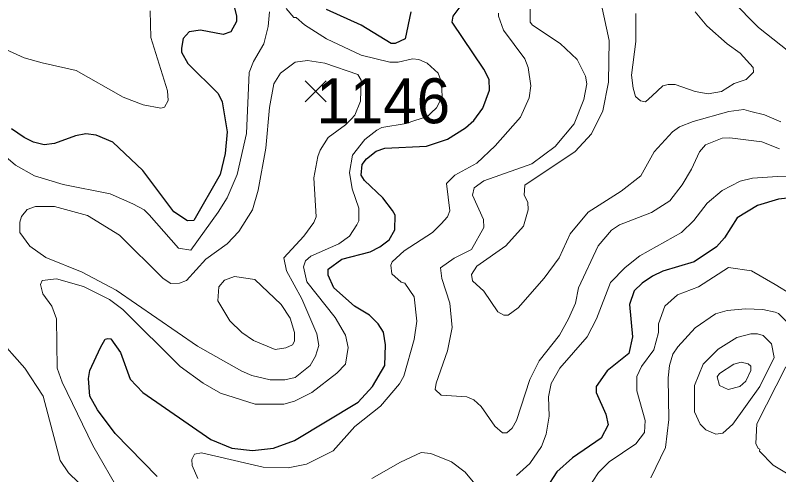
# Model space of a CAD drawing. Extents: x 423 to 448.8, y 7456.3 to 7484.
# Drawn here: x 423.744 to 425.103, y 7470.707 to 7471.525 of the extents above; entities that cross this region are included whole.
import ezdxf
from ezdxf.enums import TextEntityAlignment as Align

# ---------------------------------------------------------------- set-up
doc = ezdxf.new("R2010")
doc.units = 0
doc.header["$LTSCALE"] = 0.032
for name, color, linetype, lineweight in [('1', 7, 'Continuous', 25), ('2', 7, 'Continuous', 13), ('21', 7, 'Continuous', 25)]:
    doc.layers.add(name, color=color, linetype=linetype, lineweight=lineweight)
doc.layers.add('61', color=7, linetype='Continuous')

msp = doc.modelspace()

# ---------------------------------------------------------------- linework, layer by layer
at = {"layer": '1'}
for points in [[(424.1238, 7471.5788), (424.1378, 7471.5231), (424.1378, 7471.5138), (424.1277, 7471.4952), (424.1138, 7471.4906), (424.0736, 7471.4984), (424.0535, 7471.4953), (424.0426, 7471.4836), (424.0395, 7471.4659), (424.0395, 7471.4589), (424.0512, 7471.4388), (424.1053, 7471.3854), (424.1122, 7471.3707), (424.1208, 7471.3174), (424.1177, 7471.2787), (424.1084, 7471.2416), (424.062, 7471.1596), (424.0504, 7471.1588), (424.0264, 7471.175), (423.9707, 7471.2485), (423.9174, 7471.2988), (423.888, 7471.3112), (423.8694, 7471.3135), (423.8509, 7471.3104), (423.8137, 7471.2965), (423.7952, 7471.2941), (423.7766, 7471.2988), (423.7595, 7471.3073), (423.7371, 7471.3228)], [(423.9962, 7470.704), (423.922, 7470.7806), (423.8903, 7470.8224), (423.8764, 7470.8471), (423.874, 7470.8781), (423.8764, 7470.8927), (423.8957, 7470.9337), (423.9037, 7470.9485), (423.9084, 7470.9493), (423.9089, 7470.9493), (423.9143, 7470.9492), (423.9313, 7470.9245), (423.9483, 7470.8773), (423.9707, 7470.8533), (424.0922, 7470.7698), (424.1293, 7470.7543), (424.1664, 7470.7504), (424.2036, 7470.7543), (424.2407, 7470.7682), (424.3544, 7470.8363), (424.3799, 7470.8641), (424.4015, 7470.9013), (424.4031, 7470.9384), (424.3992, 7470.9608), (424.3899, 7470.9755), (424.3745, 7470.991), (424.3474, 7471.0072), (424.3111, 7471.0397), (424.301, 7471.0621), (424.301, 7471.073), (424.325, 7471.0907), (424.3753, 7471.1039), (424.393, 7471.1124), (424.4092, 7471.1248), (424.4193, 7471.1426), (424.4201, 7471.1688), (424.4155, 7471.1774), (424.3984, 7471.1998), (424.3652, 7471.2307), (424.3598, 7471.24), (424.3613, 7471.2593), (424.369, 7471.2694), (424.3861, 7471.2826), (424.4016, 7471.288), (424.4758, 7471.2918), (424.5129, 7471.3042), (424.5454, 7471.3243), (424.5601, 7471.3375), (424.5763, 7471.3591), (424.588, 7471.3916), (424.5872, 7471.4102), (424.5779, 7471.4288), (424.5214, 7471.5123), (424.523, 7471.5231), (424.5516, 7471.5618)], [(424.448, 7471.5309), (424.4379, 7471.4829), (424.4201, 7471.4744), (424.4131, 7471.4744), (424.3598, 7471.5069), (424.2979, 7471.5347)], [(425.1394, 7471.2014), (425.1023, 7471.1975), (425.0652, 7471.1859), (425.0288, 7471.1642), (425.0064, 7471.1287), (424.9917, 7471.1124), (424.9523, 7471.0861), (424.8966, 7471.0691), (424.878, 7471.0606), (424.8594, 7471.0482), (424.8455, 7471.0343), (424.837, 7471.0103), (424.8424, 7470.9523), (424.8362, 7470.9229), (424.7976, 7470.8919), (424.7775, 7470.8641), (424.7775, 7470.8533), (424.7952, 7470.8146), (424.7991, 7470.7961), (424.7867, 7470.7721), (424.7357, 7470.7373), (424.7078, 7470.7125), (424.6893, 7470.6839)]]:
    msp.add_lwpolyline(points, dxfattribs=at)
at = {"layer": '2'}
for points in [[(424.7867, 7471.5455), (424.8007, 7471.4798), (424.7999, 7471.4056), (424.7898, 7471.3545), (424.7697, 7471.3135), (424.7403, 7471.2825), (424.6506, 7471.2222), (424.6498, 7471.2045), (424.656, 7471.1921), (424.6568, 7471.1782), (424.6483, 7471.1495), (424.6173, 7471.1147), (424.5655, 7471.0784), (424.5562, 7471.0637)], [(425.1317, 7471.4512), (425.0667, 7471.503), (425.0195, 7471.551)], [(423.9839, 7471.5324), (423.9854, 7471.4852), (424.0148, 7471.3901), (424.0163, 7471.3731), (424.0094, 7471.3614), (424.0032, 7471.3591), (423.9715, 7471.3653), (423.9359, 7471.3792), (423.8524, 7471.4264), (423.7921, 7471.4403), (423.7596, 7471.4488), (423.7271, 7471.4635), (423.6513, 7471.5138), (423.618, 7471.5293)], [(424.226, 7471.537), (424.2399, 7471.5208), (424.2438, 7471.5208), (424.2585, 7471.5077), (424.2979, 7471.4829), (424.3598, 7471.4535), (424.4108, 7471.4411), (424.4255, 7471.4411), (424.4511, 7471.4473), (424.4619, 7471.4458), (424.4773, 7471.4396), (424.4967, 7471.4218), (424.5027, 7471.4057), (424.5035, 7471.3794), (424.4936, 7471.3598), (424.4839, 7471.3512), (424.4783, 7471.3452), (424.474, 7471.3435), (424.455, 7471.3375), (424.4396, 7471.3322), (424.3961, 7471.3247), (424.3876, 7471.3205), (424.366, 7471.3034), (424.3443, 7471.2756), (424.3389, 7471.2447), (424.3435, 7471.216), (424.3551, 7471.1813), (424.3551, 7471.1588), (424.3521, 7471.1519), (424.3389, 7471.1317), (424.3195, 7471.1178), (424.2701, 7471.0961), (424.2607, 7471.0876), (424.2569, 7471.0768), (424.2631, 7471.0505), (424.3133, 7470.9871), (424.3319, 7470.9554), (424.3366, 7470.9337), (424.3319, 7470.9036), (424.3165, 7470.8881), (424.2716, 7470.8533), (424.2407, 7470.8378), (424.2221, 7470.8324), (424.1711, 7470.8324), (424.1092, 7470.8525), (424.0783, 7470.8703), (424.0372, 7470.8997), (423.9351, 7471.001), (423.9119, 7471.0188), (423.8655, 7471.042), (423.8176, 7471.0559), (423.7921, 7471.0529), (423.789, 7471.0459), (423.7928, 7471.0289)], [(424.6606, 7471.5355), (424.6606, 7471.5123), (424.6645, 7471.5069), (424.714, 7471.4744), (424.7442, 7471.4458), (424.7589, 7471.4164), (424.7612, 7471.4025), (424.7558, 7471.3746), (424.7387, 7471.3313), (424.7048, 7471.291), (424.663, 7471.2601)], [(423.7054, 7471.2911), (423.7441, 7471.2578), (423.7782, 7471.2392), (423.8292, 7471.2238), (423.9127, 7471.2067), (423.953, 7471.189), (423.9731, 7471.1782), (423.9823, 7471.1696), (424.0342, 7471.1101), (424.0566, 7471.107), (424.1053, 7471.1743), (424.1208, 7471.1998), (424.1386, 7471.2416), (424.1556, 7471.3143), (424.1602, 7471.4226), (424.168, 7471.4427), (424.1865, 7471.4736), (424.1943, 7471.5046), (424.1966, 7471.5308)], [(424.6127, 7471.4983), (424.6042, 7471.5231), (424.6042, 7471.5285)], [(424.9538, 7471.5309), (424.9747, 7471.5061), (425.011, 7471.4736), (425.0342, 7471.4573), (425.0574, 7471.4318), (425.0578, 7471.4237), (425.045, 7471.4102), (425.0234, 7471.4032), (425.001, 7471.3893), (424.977, 7471.3847), (424.9538, 7471.3893), (424.9182, 7471.4017), (424.9059, 7471.4017), (424.8965, 7471.3993), (424.8772, 7471.3816), (424.8656, 7471.3707), (424.8564, 7471.3723), (424.8478, 7471.38), (424.8439, 7471.3947), (424.8409, 7471.4179), (424.8486, 7471.4783), (424.8486, 7471.5278)], [(424.069, 7470.7001), (424.0589, 7470.7234), (424.0581, 7470.7342), (424.0627, 7470.7434), (424.0752, 7470.7458), (424.185, 7470.7203), (424.2299, 7470.7195), (424.2623, 7470.7257), (424.3095, 7470.7496), (424.3482, 7470.793), (424.3938, 7470.8293), (424.4279, 7470.8687), (424.4356, 7470.8827), (424.4541, 7470.9477), (424.4588, 7470.9802), (424.4541, 7471.0235), (424.4371, 7471.0482), (424.4309, 7471.0498), (424.4139, 7471.0644), (424.4124, 7471.0799), (424.4147, 7471.0861), (424.4363, 7471.1055), (424.4866, 7471.1379), (424.5021, 7471.1534), (424.5129, 7471.1658), (424.5176, 7471.1766), (424.5114, 7471.2253), (424.5261, 7471.24), (424.5655, 7471.2617), (424.598, 7471.2926), (424.6429, 7471.3436), (424.6583, 7471.3777), (424.6614, 7471.3994), (424.6568, 7471.4319), (424.6506, 7471.4473), (424.6127, 7471.4983)], [(424.5562, 7471.0637), (424.5578, 7471.0521), (424.5779, 7471.0335), (424.6026, 7470.9971), (424.6135, 7470.9909), (424.6212, 7470.9909), (424.639, 7471.0041), (424.6854, 7471.0567), (424.7117, 7471.0931), (424.7318, 7471.1356), (424.7635, 7471.1743), (424.8223, 7471.2114), (424.8571, 7471.2392), (424.8811, 7471.2818), (424.9136, 7471.3173), (424.926, 7471.3259), (424.9507, 7471.3359), (425.0141, 7471.3537), (425.0404, 7471.3568), (425.0528, 7471.3537), (425.0776, 7471.3475), (425.1062, 7471.3351)], [(424.663, 7471.2601), (424.5779, 7471.23), (424.5609, 7471.2176), (424.5578, 7471.2045), (424.5771, 7471.1611), (424.5779, 7471.1472), (424.5562, 7471.1078), (424.5253, 7471.0923), (424.5006, 7471.0753), (424.5029, 7471.056), (424.5175, 7471.0126), (424.5214, 7470.9693), (424.5129, 7470.9276), (424.4928, 7470.8703), (424.4913, 7470.8587), (424.5021, 7470.8486), (424.5477, 7470.8456), (424.5601, 7470.8401), (424.5732, 7470.8286), (424.5972, 7470.7937), (424.6111, 7470.7814), (424.6189, 7470.7814), (424.6282, 7470.7899), (424.6359, 7470.8038), (424.6599, 7470.8765), (424.6761, 7470.9097), (424.7125, 7470.9554), (424.7287, 7470.9848), (424.7411, 7471.0126), (424.7465, 7471.0397), (424.7813, 7471.1147), (424.8053, 7471.1425), (424.8192, 7471.1518), (424.8765, 7471.1735), (424.9089, 7471.1944), (424.9306, 7471.223), (424.9476, 7471.2509), (424.9615, 7471.2818), (424.9724, 7471.2941), (425.0018, 7471.3058), (425.0157, 7471.3066), (425.0729, 7471.2996), (425.1039, 7471.2872)], [(425.1333, 7471.2369), (425.1008, 7471.2377), (425.0559, 7471.2346), (425.0343, 7471.2292), (425.0018, 7471.213), (424.9754, 7471.1905), (424.9515, 7471.1596), (424.9298, 7471.1379), (424.8556, 7471.0969), (424.8293, 7471.076), (424.803, 7471.049), (424.7782, 7470.9848), (424.762, 7470.9523), (424.7132, 7470.8966), (424.6978, 7470.8695), (424.6931, 7470.8456), (424.6939, 7470.8115), (424.6885, 7470.7791), (424.6807, 7470.7574), (424.6599, 7470.7272), (424.6359, 7470.7056)], [(424.762, 7470.6801), (424.7821, 7470.7109), (424.8007, 7470.7303), (424.8486, 7470.762), (424.864, 7470.7821), (424.8648, 7470.8038), (424.8502, 7470.8564), (424.8502, 7470.8819), (424.8586, 7470.8997), (424.8803, 7470.9291), (424.8888, 7470.96), (424.8888, 7470.9755), (424.8997, 7471.0072), (424.9228, 7471.0273), (424.96, 7471.0412), (425.0133, 7471.076), (425.0544, 7471.0699), (425.0961, 7471.0459), (425.1255, 7471.0281)], [(423.7928, 7471.0289), (423.8091, 7471.0072), (423.8176, 7470.9848), (423.8184, 7470.8966), (423.8276, 7470.8719), (423.8818, 7470.7589), (423.9313, 7470.6739)], [(425.1232, 7470.9732), (425.1023, 7470.9941), (425.0961, 7470.9964), (425.0745, 7471.001), (425.0435, 7471.0026), (425.011, 7470.9995), (424.9901, 7470.9933), (424.9538, 7470.9685), (424.9229, 7470.9345), (424.9143, 7470.9214), (424.9081, 7470.9013), (424.9059, 7470.8796), (424.9074, 7470.8054), (424.9012, 7470.7558), (424.8749, 7470.7017)], [(423.8748, 7470.6754), (423.8385, 7470.7102), (423.8238, 7470.7327), (423.7936, 7470.8471), (423.7611, 7470.8966), (423.71, 7470.9539)], [(425.1193, 7470.7079), (425.093, 7470.7241), (425.0683, 7470.7489), (425.069, 7470.7528), (425.0659, 7470.7535), (425.0621, 7470.7628), (425.0636, 7470.7976), (425.1154, 7470.8989)], [(424.5871, 7470.6599), (424.5446, 7470.7117), (424.5206, 7470.7303), (424.4835, 7470.745), (424.4665, 7470.7465), (424.4294, 7470.7296), (424.3784, 7470.7001)]]:
    msp.add_lwpolyline(points, dxfattribs=at)
for points in [[(423.8725, 7471.1681), (423.8137, 7471.1843), (423.7797, 7471.1843), (423.765, 7471.1789), (423.7549, 7471.1665), (423.7518, 7471.1565), (423.7518, 7471.1379), (423.7696, 7471.1139), (423.7983, 7471.0938), (423.8632, 7471.0675), (423.9236, 7471.0358), (424.0682, 7470.936), (424.1471, 7470.8912), (424.1649, 7470.8834), (424.1974, 7470.8757), (424.2237, 7470.8757), (424.2422, 7470.8803), (424.2685, 7470.9013), (424.2785, 7470.9183), (424.284, 7470.9368), (424.2809, 7470.9577), (424.2538, 7471.0204), (424.2268, 7471.0699), (424.2221, 7471.0931), (424.2577, 7471.1317), (424.2755, 7471.1557), (424.2793, 7471.1658), (424.2755, 7471.2354), (424.2824, 7471.2733), (424.2863, 7471.2849), (424.301, 7471.3073), (424.3314, 7471.3299), (424.342, 7471.3399), (424.3483, 7471.3472), (424.3583, 7471.3721), (424.3596, 7471.4093), (424.3539, 7471.4192), (424.2948, 7471.4396), (424.2639, 7471.4442), (424.2422, 7471.4411), (424.2159, 7471.4218), (424.2043, 7471.4025), (424.1966, 7471.3607), (424.1896, 7471.288), (424.1765, 7471.2137), (424.1664, 7471.1782), (424.1417, 7471.1402), (424.1208, 7471.1178), (424.0828, 7471.0907), (424.0488, 7471.0528), (424.0365, 7471.0482), (424.021, 7471.0474), (424.007, 7471.056), (423.9297, 7471.1333)], [(424.1258, 7470.9809), (424.1045, 7471.0165), (424.1061, 7471.0412), (424.1161, 7471.0536), (424.1339, 7471.0598), (424.1703, 7471.0544), (424.2174, 7471.0103), (424.2329, 7470.9855), (424.2407, 7470.96), (424.2407, 7470.9445), (424.2376, 7470.9383), (424.2252, 7470.9329), (424.2066, 7470.9298), (424.168, 7470.9461), (424.1471, 7470.96)], [(425.0211, 7470.7968), (425.069, 7470.8641), (425.0946, 7470.9159), (425.0899, 7470.9399), (425.0752, 7470.9546), (425.0652, 7470.9577), (425.0528, 7470.9577), (425.0281, 7470.9515), (424.9948, 7470.9306), (424.9685, 7470.9036), (424.953, 7470.8657), (424.953, 7470.8193), (424.9631, 7470.7968), (424.9731, 7470.7867), (424.9909, 7470.7791), (425.0033, 7470.7813)], [(425.0226, 7470.9036), (425.0358, 7470.9074), (425.0482, 7470.9043), (425.0528, 7470.9005), (425.0528, 7470.8927), (425.0443, 7470.8734), (425.0334, 7470.8641), (425.0126, 7470.8587), (424.9971, 7470.8656), (424.9932, 7470.8812), (424.9971, 7470.8873)]]:
    msp.add_lwpolyline(points, close=True, dxfattribs=at)
at = {"layer": '21'}
for p, q in [((424.2599, 7471.4079), (424.2974, 7471.3704)), ((424.2974, 7471.4079), (424.2599, 7471.3704))]:
    msp.add_line(p, q, dxfattribs=at)

# ---------------------------------------------------------------- texts
at = {"layer": '61'}
msp.add_text('1146', height=0.08, dxfattribs=at).set_placement((424.3988, 7471.3325), align=Align.CENTER)

doc.saveas('drawing.dxf')
